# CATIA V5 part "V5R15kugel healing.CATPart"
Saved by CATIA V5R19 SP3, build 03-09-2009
Part number: Part1
Bounding box of the stored display mesh (mm): x -199.986 to 199.986, y -200.1 to 200, z -200.1 to 200.1
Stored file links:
  C:\2009-V5\V5R15kugel healing.CATPart
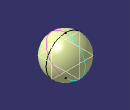
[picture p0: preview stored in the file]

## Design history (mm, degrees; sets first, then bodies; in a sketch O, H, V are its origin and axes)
Set1
  Sphere1: Center {point type Coord, X 0, Y 0, Z 0}, Radius 200, Angle1 -45, Angle3 0, Angle4 180
  Offset1: Offset Sphere1, Length 0.1
  Split1: ToCut Sphere1, Cutting zx-plane
  Split2: ToCut Offset1, Cutting zx-plane
  MultiSel1
  Join1 "Join0,1mm": Elements (Split2; Split1)
  Healing1 "Healing.0,1mm und 0,001": BodyToHeal (Split2; Split1), TangencyAngle 0.5, SharpnessAngle 0.5
Body1 (main body)
Body2 "Body.join 0,1"
  CloseSurface1: CloseElement Join1
  Set2
    Intersect1: ToIntersect1 CloseSurface1, ToIntersect2 yz-plane
    DatumCurve1
    DatumCurve2
Body3
  CloseSurface2: CloseElement Healing1
  Set3 "Geometrical Set.bei 0,001mm meckert der intersect. bei 0,1mm nicht"
    Intersect2: ToIntersect1 CloseSurface2, ToIntersect2 yz-plane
